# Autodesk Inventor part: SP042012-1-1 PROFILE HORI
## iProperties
Created: 2013-01
Part Number: SP042012-1-1 PROFILE HORI
Material: Aluminum-6061
Description: PROFILE 45X45 UL
Document SubType Name: Modeling
Designer: Administrator
Stock Number: 20.1063 PROFILE 45X45 UL
Density: 2.71 g/cm^3
Mass: 1775.23 g
Surface Area: 7771.49 cm^2
Volume: 655.068 cm^3
FINISH: CLEAR ANODIZED
Author: Administrator
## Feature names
1. Extrusion1
